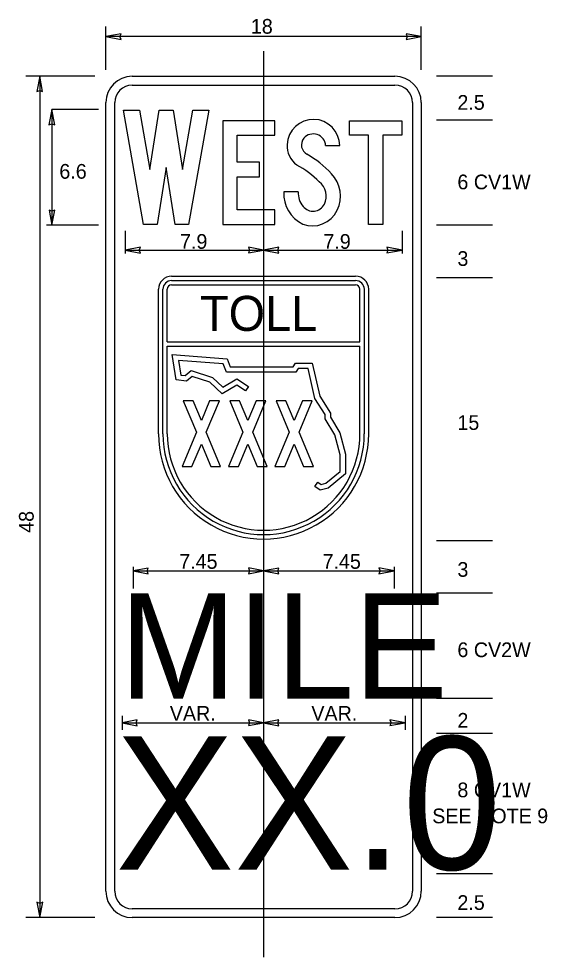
# Model space of a CAD drawing. Extents: x 56108 to 56734, y 11696 to 12110.
# Drawn here: x 56513 to 56613.6, y 11931.8 to 12110.3 of the extents above; entities that cross this region are included whole.
import ezdxf

# ---------------------------------------------------------------- set-up
doc = ezdxf.new("R2010")
doc.units = 0
for name, color, linetype in [('CL_dp', 7, 'Continuous'), ('GSDims', 7, 'Continuous'), ('SignDetail', 7, 'Continuous'), ('SignPanel', 7, 'Continuous')]:
    doc.layers.add(name, color=color, linetype=linetype)

msp = doc.modelspace()

# ---------------------------------------------------------------- linework, layer by layer
at = {"layer": 'CL_dp'}
msp.add_line((56559.63, 12104.19), (56559.63, 11931.84), dxfattribs=at)
at = {"layer": 'GSDims'}
for p, q in [((56529.63, 12100.62), (56529.63, 12108.84)), ((56589.63, 12100.62), (56589.63, 12108.84)), ((56532.53, 12107.46), (56529.63, 12106.92)), ((56589.63, 12106.92), (56529.63, 12106.92)), ((56529.63, 12106.92), (56532.53, 12106.36)), ((56532.31, 12106.92), (56532.53, 12107.46)), ((56532.53, 12106.36), (56532.31, 12106.92)), ((56589.63, 12106.92), (56586.73, 12107.48)), ((56586.73, 12107.48), (56586.95, 12106.92)), ((56586.95, 12106.92), (56586.73, 12106.38)), ((56586.73, 12106.38), (56589.63, 12106.92)), ((56527.55, 12099.38), (56514.42, 12099.38)), ((56517.04, 12099.38), (56516.48, 12096.48)), ((56517.04, 12099.38), (56517.04, 11939.38)), ((56517.58, 12096.48), (56517.04, 12099.38)), ((56603.18, 12099.38), (56592.5, 12099.38)), ((56516.48, 12096.48), (56517.04, 12096.7)), ((56517.04, 12096.7), (56517.58, 12096.48)), ((56519.35, 12093.05), (56518.79, 12090.15)), ((56519.35, 12093.05), (56519.35, 12071.05)), ((56528.22, 12093.05), (56519.35, 12093.05)), ((56519.89, 12090.15), (56519.35, 12093.05)), ((56603.18, 12091.05), (56592.5, 12091.05)), ((56518.79, 12090.15), (56519.35, 12090.37)), ((56519.35, 12090.37), (56519.89, 12090.15)), ((56519.35, 12073.73), (56518.81, 12073.95)), ((56518.81, 12073.95), (56519.35, 12071.05)), ((56519.35, 12071.05), (56519.91, 12073.95)), ((56519.91, 12073.95), (56519.35, 12073.73)), ((56528.22, 12071.05), (56518.3, 12071.05)), ((56603.18, 12071.05), (56592.5, 12071.05)), ((56533.3, 12069.96), (56533.3, 12065.71)), ((56585.97, 12069.96), (56585.97, 12065.71)), ((56536.2, 12066.87), (56533.3, 12066.33)), ((56533.3, 12066.33), (56559.63, 12066.33)), ((56533.3, 12066.33), (56536.2, 12065.77)), ((56535.98, 12066.33), (56536.2, 12066.87)), ((56536.2, 12065.77), (56535.98, 12066.33)), ((56559.63, 12066.33), (56556.73, 12066.89)), ((56556.73, 12066.89), (56556.95, 12066.33)), ((56556.95, 12066.33), (56556.73, 12065.79)), ((56556.73, 12065.79), (56559.63, 12066.33)), ((56562.53, 12066.87), (56559.63, 12066.33)), ((56559.63, 12066.33), (56585.97, 12066.33)), ((56559.63, 12066.33), (56562.53, 12065.77)), ((56562.31, 12066.33), (56562.53, 12066.87)), ((56562.53, 12065.77), (56562.31, 12066.33)), ((56585.97, 12066.33), (56583.07, 12066.89)), ((56583.07, 12066.89), (56583.29, 12066.33)), ((56583.29, 12066.33), (56583.07, 12065.79)), ((56583.07, 12065.79), (56585.97, 12066.33)), ((56603.18, 12061.05), (56592.5, 12061.05)), ((56547.76, 12044.95), (56547.76, 12044.95)), ((56603.18, 12011.05), (56592.5, 12011.05)), ((56534.8, 12006.1), (56534.8, 12001.97)), ((56537.7, 12005.85), (56534.8, 12005.31)), ((56534.8, 12005.31), (56559.63, 12005.31)), ((56534.8, 12005.31), (56537.7, 12004.75)), ((56537.48, 12005.31), (56537.7, 12005.85)), ((56537.7, 12004.75), (56537.48, 12005.31)), ((56559.63, 12005.31), (56556.73, 12005.87)), ((56556.73, 12005.87), (56556.95, 12005.31)), ((56556.95, 12005.31), (56556.73, 12004.77)), ((56556.73, 12004.77), (56559.63, 12005.31)), ((56562.53, 12005.85), (56559.63, 12005.31)), ((56559.63, 12005.31), (56584.47, 12005.31)), ((56559.63, 12005.31), (56562.53, 12004.75)), ((56562.31, 12005.31), (56562.53, 12005.85)), ((56562.53, 12004.75), (56562.31, 12005.31)), ((56584.47, 12005.31), (56581.57, 12005.87)), ((56581.57, 12005.87), (56581.79, 12005.31)), ((56581.79, 12005.31), (56581.57, 12004.77)), ((56581.57, 12004.77), (56584.47, 12005.31)), ((56584.47, 12006.1), (56584.47, 12001.97)), ((56603.18, 12001.05), (56592.5, 12001.05)), ((56603.18, 11981.05), (56592.5, 11981.05)), ((56532.7, 11977.77), (56532.7, 11975.08)), ((56535.6, 11976.96), (56532.7, 11976.42)), ((56532.7, 11976.42), (56559.63, 11976.42)), ((56532.7, 11976.42), (56535.6, 11975.86)), ((56535.38, 11976.42), (56535.6, 11976.96)), ((56535.6, 11975.86), (56535.38, 11976.42)), ((56559.63, 11976.42), (56556.73, 11976.98)), ((56556.73, 11976.98), (56556.95, 11976.42)), ((56556.95, 11976.42), (56556.73, 11975.88)), ((56556.73, 11975.88), (56559.63, 11976.42)), ((56562.53, 11976.96), (56559.63, 11976.42)), ((56559.63, 11976.42), (56562.53, 11975.86)), ((56559.63, 11976.42), (56586.57, 11976.42)), ((56562.31, 11976.42), (56562.53, 11976.96)), ((56562.53, 11975.86), (56562.31, 11976.42)), ((56586.57, 11976.42), (56583.67, 11976.98)), ((56583.67, 11976.98), (56583.89, 11976.42)), ((56583.89, 11976.42), (56583.67, 11975.88)), ((56583.67, 11975.88), (56586.57, 11976.42)), ((56586.57, 11977.77), (56586.57, 11975.08)), ((56603.18, 11974.38), (56592.5, 11974.38)), ((56603.18, 11947.71), (56592.5, 11947.71)), ((56517.04, 11942.06), (56516.5, 11942.28)), ((56516.5, 11942.28), (56517.04, 11939.38)), ((56517.04, 11939.38), (56517.6, 11942.28)), ((56517.6, 11942.28), (56517.04, 11942.06)), ((56527.55, 11939.38), (56514.42, 11939.38)), ((56603.18, 11939.38), (56592.5, 11939.38))]:
    msp.add_line(p, q, dxfattribs=at)
at = {"layer": 'SignDetail'}
for p, q in [((56542.13, 12061.38), (56577.14, 12061.38)), ((56542.13, 12060.54), (56577.14, 12060.54)), ((56539.64, 12031.37), (56539.64, 12058.88)), ((56540.48, 12031.37), (56540.48, 12058.88)), ((56541.3, 12048.89), (56541.3, 12058.88)), ((56542.13, 12059.7), (56577.14, 12059.7)), ((56577.96, 12048.89), (56577.96, 12058.88)), ((56578.8, 12031.37), (56578.8, 12058.88)), ((56579.64, 12031.37), (56579.64, 12058.88)), ((56541.3, 12048.89), (56577.96, 12048.89)), ((56541.3, 12031.37), (56541.3, 12048.05)), ((56541.3, 12048.05), (56577.96, 12048.05)), ((56577.96, 12031.37), (56577.96, 12048.05))]:
    msp.add_line(p, q, dxfattribs=at)
for centre, major_axis, start_param, end_param in [((56542.14, 12058.87), (0, 2.5), 0, 1.570796), ((56542.14, 12058.87), (0, 1.67), 0, 1.570796), ((56577.13, 12058.87), (0, 2.5), 4.712389, 6.283185), ((56577.13, 12058.87), (0, 1.67), 4.712389, 6.283185), ((56542.14, 12058.87), (0, 0.833), 0, 1.570796), ((56577.13, 12058.87), (0, 0.833), 4.712389, 6.283185), ((56559.64, 12031.38), (0, -20), 4.712389, 7.853982), ((56559.64, 12031.38), (0, -19.16), 4.712389, 7.853982), ((56559.64, 12031.38), (0, -18.33), 4.712389, 7.853982)]:
    msp.add_ellipse(centre, major_axis=major_axis, ratio=0.9997, start_param=start_param, end_param=end_param, dxfattribs=at)
at = {"layer": 'SignPanel'}
for p, q in [((56571.44, 12086.19), (56574.13, 12086.19)), ((56571.44, 12086.19), (56574.13, 12086.19)), ((56571.44, 12086.19), (56574.13, 12086.19)), ((56566.2, 12077.39), (56563.47, 12077.39)), ((56566.2, 12077.39), (56563.47, 12077.39)), ((56566.2, 12077.39), (56563.47, 12077.39)), ((56542.98, 12041.66), (56542.24, 12046.44)), ((56542.24, 12046.44), (56552.67, 12045.63)), ((56551.96, 12044.68), (56543.43, 12045.33)), ((56543.43, 12045.33), (56543.86, 12042.57)), ((56552.57, 12043.12), (56551.96, 12044.68)), ((56552.67, 12045.63), (56553.26, 12044.13)), ((56553.26, 12044.13), (56565.23, 12044.13)), ((56565.23, 12044.13), (56565.68, 12044.8)), ((56565.68, 12044.8), (56568.9, 12044.8)), ((56568.9, 12044.8), (56570.35, 12038.52)), ((56543.86, 12042.57), (56544.69, 12042.47)), ((56544.69, 12042.47), (56545.87, 12043.4)), ((56546.07, 12042.28), (56544.98, 12041.42)), ((56545.87, 12043.4), (56549.9, 12042.09)), ((56549.38, 12041.2), (56546.07, 12042.28)), ((56565.76, 12043.12), (56552.57, 12043.12)), ((56566.21, 12043.79), (56565.76, 12043.12)), ((56568.1, 12043.79), (56566.21, 12043.79)), ((56569.41, 12038.13), (56568.1, 12043.79)), ((56544.98, 12041.42), (56542.98, 12041.66)), ((56551.74, 12039.01), (56549.38, 12041.2)), ((56549.9, 12042.09), (56551.87, 12040.26)), ((56554.51, 12040.64), (56551.74, 12039.01)), ((56551.87, 12040.26), (56554.55, 12041.83)), ((56556.17, 12039.53), (56554.51, 12040.64)), ((56554.55, 12041.83), (56556.73, 12040.36)), ((56556.73, 12040.36), (56556.17, 12039.53)), ((56571.33, 12035.05), (56569.41, 12038.13)), ((56570.35, 12038.52), (56572.34, 12035.33)), ((56572.34, 12035.33), (56572.34, 12034.53)), ((56571.33, 12034.25), (56571.33, 12035.05)), ((56573.2, 12031.17), (56571.33, 12034.25)), ((56572.34, 12034.53), (56574.13, 12031.57)), ((56574.13, 12031.57), (56575.24, 12027.53)), ((56574.23, 12027.39), (56573.2, 12031.17)), ((56574.23, 12024.23), (56574.23, 12027.39)), ((56575.24, 12027.53), (56575.24, 12023.75)), ((56571.48, 12021.97), (56574.23, 12024.23)), ((56575.24, 12023.75), (56571.94, 12021.05)), ((56569.39, 12021.36), (56569.96, 12022.19)), ((56570.38, 12020.67), (56569.39, 12021.36)), ((56569.96, 12022.19), (56570.58, 12021.76)), ((56571.94, 12021.05), (56570.38, 12020.67)), ((56570.58, 12021.76), (56571.48, 12021.97))]:
    msp.add_line(p, q, dxfattribs=at)
for points in [[(56534.63, 12099.38), (56584.63, 12099.38)], [(56534.63, 12097.71), (56584.63, 12097.71)], [(56529.63, 11944.38), (56529.63, 12094.38)], [(56531.3, 11944.38), (56531.3, 12094.38)], [(56587.97, 12094.38), (56587.97, 11944.38)], [(56589.63, 12094.38), (56589.63, 11944.38)], [(56584.63, 11941.05), (56534.63, 11941.05)], [(56584.63, 11939.38), (56534.63, 11939.38)]]:
    msp.add_lwpolyline(points, dxfattribs=at)
for points in [[(56538, 12081.68), (56539.77, 12092.92), (56542.42, 12092.92), (56544.19, 12081.68), (56546.18, 12092.92), (56549.22, 12092.92), (56545.37, 12071.2), (56542.8, 12071.2), (56541.09, 12082.06), (56539.38, 12071.2), (56536.81, 12071.2), (56532.96, 12092.92), (56536.01, 12092.92)], [(56538, 12081.68), (56539.77, 12092.92), (56542.42, 12092.92), (56544.19, 12081.68), (56546.18, 12092.92), (56549.22, 12092.92), (56545.37, 12071.2), (56542.8, 12071.2), (56541.09, 12082.06), (56539.38, 12071.2), (56536.81, 12071.2), (56532.96, 12092.92), (56536.01, 12092.92)], [(56538, 12081.68), (56539.77, 12092.92), (56542.42, 12092.92), (56544.19, 12081.68), (56546.18, 12092.92), (56549.22, 12092.92), (56545.37, 12071.2), (56542.8, 12071.2), (56541.09, 12082.06), (56539.38, 12071.2), (56536.81, 12071.2), (56532.96, 12092.92), (56536.01, 12092.92)], [(56554.58, 12073.96), (56554.58, 12080.28), (56558.84, 12080.28), (56558.84, 12083.05), (56554.58, 12083.05), (56554.58, 12088.18), (56561.77, 12088.18), (56561.77, 12090.94), (56551.86, 12090.94), (56551.86, 12071.2), (56561.77, 12071.2), (56561.77, 12073.96)], [(56554.58, 12073.96), (56554.58, 12080.28), (56558.84, 12080.28), (56558.84, 12083.05), (56554.58, 12083.05), (56554.58, 12088.18), (56561.77, 12088.18), (56561.77, 12090.94), (56551.86, 12090.94), (56551.86, 12071.2), (56561.77, 12071.2), (56561.77, 12073.96)], [(56554.58, 12073.96), (56554.58, 12080.28), (56558.84, 12080.28), (56558.84, 12083.05), (56554.58, 12083.05), (56554.58, 12088.18), (56561.77, 12088.18), (56561.77, 12090.94), (56551.86, 12090.94), (56551.86, 12071.2), (56561.77, 12071.2), (56561.77, 12073.96)], [(56579.6, 12088.18), (56576, 12088.18), (56576, 12090.94), (56585.92, 12090.94), (56585.92, 12088.18), (56582.32, 12088.18), (56582.32, 12071.2), (56579.6, 12071.2)], [(56579.6, 12088.18), (56576, 12088.18), (56576, 12090.94), (56585.92, 12090.94), (56585.92, 12088.18), (56582.32, 12088.18), (56582.32, 12071.2), (56579.6, 12071.2)], [(56579.6, 12088.18), (56576, 12088.18), (56576, 12090.94), (56585.92, 12090.94), (56585.92, 12088.18), (56582.32, 12088.18), (56582.32, 12071.2), (56579.6, 12071.2)], [(56546, 12025.15), (56547.79, 12029.43), (56549.58, 12025.15), (56551.45, 12025.15), (56548.72, 12031.67), (56551.23, 12037.65), (56549.36, 12037.65), (56547.79, 12033.9), (56546.22, 12037.65), (56544.34, 12037.65), (56546.85, 12031.67), (56544.12, 12025.15)], [(56554.83, 12025.15), (56556.62, 12029.43), (56558.41, 12025.15), (56560.29, 12025.15), (56557.56, 12031.67), (56560.07, 12037.65), (56558.19, 12037.65), (56556.62, 12033.9), (56555.05, 12037.65), (56553.18, 12037.65), (56555.69, 12031.67), (56552.96, 12025.15)], [(56563.67, 12025.15), (56565.46, 12029.43), (56567.25, 12025.15), (56569.12, 12025.15), (56566.4, 12031.67), (56568.9, 12037.65), (56567.03, 12037.65), (56565.46, 12033.9), (56563.89, 12037.65), (56562.02, 12037.65), (56564.52, 12031.67), (56561.8, 12025.15)]]:
    msp.add_lwpolyline(points, close=True, dxfattribs=at)
for centre, radius, start, end in [((56534.63, 12094.38), 5, 90, 180), ((56584.63, 12094.38), 5, 0, 90), ((56534.63, 12094.38), 3.33, 90, 180), ((56584.63, 12094.38), 3.33, 0, 90), ((56534.63, 11944.38), 5, 180, 270), ((56534.63, 11944.38), 3.33, 180, 270), ((56584.63, 11944.38), 5, 270, 360), ((56584.63, 11944.38), 3.33, 270, 360)]:
    msp.add_arc(centre, radius, start, end, dxfattribs=at)
for centre, major_axis, start_param, end_param in [((56569.11, 12086.07), (0, 5.12), 4.736267, 7.790596), ((56569.11, 12086.07), (0, 5.12), 4.736267, 7.790596), ((56569.11, 12086.07), (0, 5.12), 4.736267, 7.790596), ((56568.79, 12086.31), (0, 1.99), 0.87378, 2.656959), ((56568.79, 12086.31), (0, 1.99), 0.87378, 2.656959), ((56568.79, 12086.31), (0, 1.99), 0.87378, 2.656959), ((56569.08, 12086.01), (0, 2.41), 4.786904, 7.140738), ((56569.08, 12086.01), (0, 2.41), 4.786904, 7.140738), ((56569.08, 12086.01), (0, 2.41), 4.786904, 7.140738), ((56568.6, 12086.23), (0, 4.6), 1.534831, 2.511766), ((56568.6, 12086.23), (0, 4.6), 1.534831, 2.511766), ((56568.6, 12086.23), (0, 4.6), 1.534831, 2.511766), ((56558.95, 12067.94), (0, 18.94), 5.462886, 5.782242), ((56558.95, 12067.94), (0, 18.94), 5.462886, 5.782242), ((56558.95, 12067.94), (0, 18.94), 5.462886, 5.782242), ((56556.6, 12064.92), (0, 20), 5.515137, 5.786988), ((56556.6, 12064.92), (0, 20), 5.515137, 5.786988), ((56556.6, 12064.92), (0, 20), 5.515137, 5.786988), ((56568.25, 12076.58), (0, 6.12), 4.260987, 5.485755), ((56568.25, 12076.58), (0, 6.12), 4.260987, 5.485755), ((56568.25, 12076.58), (0, 6.12), 4.260987, 5.485755), ((56568.2, 12076.59), (0, 3.42), 4.254409, 5.632398), ((56568.2, 12076.59), (0, 3.42), 4.254409, 5.632398), ((56568.2, 12076.59), (0, 3.42), 4.254409, 5.632398), ((56569.79, 12077.1), (0, 6.45), 1.526364, 2.701682), ((56569.79, 12077.1), (0, 6.45), 1.526364, 2.701682), ((56569.79, 12077.1), (0, 6.45), 1.526364, 2.701682), ((56570.06, 12077.21), (0, 3.93), 1.524757, 2.28214), ((56570.06, 12077.21), (0, 3.93), 1.524757, 2.28214), ((56570.06, 12077.21), (0, 3.93), 1.524757, 2.28214), ((56569.03, 12076.24), (0, 2.51), 2.261787, 4.23006), ((56569.03, 12076.24), (0, 2.51), 2.261787, 4.23006), ((56569.03, 12076.24), (0, 2.51), 2.261787, 4.23006), ((56568.93, 12076.3), (0, 5.37), 2.786047, 4.251692), ((56568.93, 12076.3), (0, 5.37), 2.786047, 4.251692), ((56568.93, 12076.3), (0, 5.37), 2.786047, 4.251692)]:
    msp.add_ellipse(centre, major_axis=major_axis, ratio=0.981197, start_param=start_param, end_param=end_param, dxfattribs=at)

# ---------------------------------------------------------------- texts
at = {"layer": 'GSDims'}
for s, p in [('18', (56557.21, 12107.48)), ('2.5', (56596.51, 12093.01)), ('6.6', (56520.77, 12079.9)), ('6 CV1W', (56596.51, 12077.89)), ('7.9', (56543.73, 12066.57)), ('7.9', (56571.01, 12066.57)), ('3', (56596.51, 12063.32)), ('15', (56596.51, 12032.13)), ('7.45', (56543.58, 12005.71)), ('7.45', (56570.85, 12005.71)), ('3', (56596.51, 12004.19)), ('6 CV2W', (56596.51, 11988.91)), ('VAR.', (56541.79, 11976.82)), ('VAR.', (56568.72, 11976.82)), ('2', (56596.51, 11975.49)), ('8 CV1W', (56596.51, 11962.26)), ('SEE NOTE 9', (56591.72, 11957.31)), ('2.5', (56596.51, 11940.84))]:
    msp.add_text(s, height=2.8, dxfattribs=at).set_placement(p)
msp.add_text('48', height=2.8, rotation=90, dxfattribs=at).set_placement((56515.89, 12012.55))
at = {"layer": 'SignDetail'}
msp.add_text('TOLL', height=6.659, dxfattribs=at).set_placement((56547.55, 12050.96))
at = {"layer": 'SignPanel'}
for s, height, p in [('MILE', 20, (56532.22, 11981.02)), ('XX.0', 25.333, (56531.45, 11948.51))]:
    msp.add_text(s, height=height, dxfattribs=at).set_placement(p)

doc.saveas('drawing.dxf')
